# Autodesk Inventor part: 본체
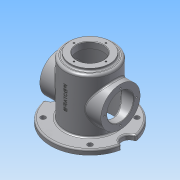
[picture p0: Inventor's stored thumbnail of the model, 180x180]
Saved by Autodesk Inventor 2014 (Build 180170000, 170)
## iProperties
Created: 2018-04
Part Number: 본체
Material: 알루미늄 6061
Document SubType Name: Modeling
Designer: user
Density: 2.71 g/cm^3
Appearance: 알루미늄 - 평지
Mass: 1151.3 g
Surface Area: 1200.36 cm^2
Volume: 424.833 cm^3
Author: user
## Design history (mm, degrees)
sketch "스케치1"
  geometry: L1 (-62, 0)-(62, 0); L2 (-62, 0)-(-62, 27); L3 (-62, 27)-(62, 27); L4 (62, 27)-(62, 0); L5 (-62, 27)-(-62, 40); L6 (-62, 40)-(62, 40); L7 (62, 40)-(62, 27); 2 further points
  constraints: 14 end point, 3 parallel, 3 perpendicular, 1 coincident, 1 horizontal, 1 midpoint
  dimensions: "d0" = 124 distance of L1.start L1.end; "d1" = 54 diameter of L3 L1; "d2" = 80 diameter of L6 L1
revolve "회전1" stored, may be unused: angle "d3" = 90 deg
sketch "스케치3"
  geometry: L1 (0, 65)-(0, -68); L2 (62, 40)-(62, -40) reference; L3 (62, -40)-(-62, -40) reference; L4 (-62, -40)-(-62, 40) reference; L5 (-62, 40)-(62, 40) reference; L6 (0, 65)-(-40, 65); L7 (-40, 65)-(-40, 60); L8 (-40, 60)-(-50, 60); L9 (-50, 60)-(-50, -68); L10 (-50, -68)-(0, -68); L11 (-27, 65)-(-27, 52); L12 (-27, 52)-(-45, 52); L13 (-45, 52)-(-45, -68); 2 further points
  constraints: 18 end point, 4 parallel, 4 perpendicular, 2 point on line, 1 midpoint, 1 vertical, 1 vertical alignment
  dimensions: "d13" = 133 distance of L1.start L1.end; "d14" = 80 diameter of L7 L1; "d15" = 100 diameter of L9 L1; "d16" = 54 diameter of L11 L1; "d17" = 90 diameter of L13 L1; "d18" = 5 distance of L6.end L7.end; "d19" = 13 distance of L11.start L11.end; "d20" = 60 distance from line of L8 point (0, 0)
  node "절단 모서리 투영2"
revolve "회전3" stored, may be unused: angle "d21" = 90 deg
node "작업 평면1"
sketch "스케치4"
  geometry: L1 (0, 0)-(47.73, 47.73); L2 (0, 0)-(67.5, 0); C1 r 50 at (0, 0) reference; C2 r 80 at (0, 0); C3 r 5 at (47.73, 47.73); C4 r 5 at (-47.73, 47.73); C5 r 5 at (-47.73, -47.73); C6 r 5 at (47.73, -47.73); 1 further point
  constraints: 5 centre point, 4 end point, 2 coincident, 1 equal length, 1 horizontal, 9 other
  dimensions: "d23" = 160 diameter of C2; "d25" = 67.5 distance of L1.start L1.end; "d26" = 45 deg angle of L2 L1; "d27" = 10 diameter of C3; "d30" = 360 deg dimension on point (0, 0) C3.centre (derived)
extrude "돌출1" join sketch "스케치4" distance "d32" = 10; taper "d33" = 0 deg
sketch "스케치5"
  geometry: C1 r 50 at (0, 0) reference; C2 r 15 at (-80, 0); C3 r 15 at (80, 0); A1 r 80 centre (0, 0) between (-80, 0) and (80, 0) reference
  constraints: 2 centre point, 2 horizontal alignment, 2 point on circle
  dimensions: "d36" = 30 diameter of C2; "d37" = 30 diameter of C3
extrude "돌출2" cut sketch "스케치5" distance "d38" = 10; taper "d39" = 0 deg
revolve "회전4" stored, may be unused: angle "d40" = 90 deg
revolve "회전5" stored, may be unused: angle "d41" = 90 deg
sketch "스케치6"
  geometry: C1 r 27 at (0, 0) reference; 4 further points
  constraints: 1 vertical alignment, 5 other
  dimensions: "d42" = 32.5 distance of C1.centre point (0, 32.5); "d45" = 360 deg dimension on C1.centre point (0, 32.5) (derived)
hole "구멍1" sketch "스케치6" at (0, 32.5), (-32.5, 0), (0, -32.5), (32.5, 0) diameter "d47" = 3.242; stored, may be unused: countersink angle "d51" = 90 deg, drill point angle "d53" = 118 deg; dims "d48" = 8, "d49" = 4, "d50" = 2, "d52" = 10
sketch "스케치7"
  geometry: C1 r 27 at (0, 0) reference; 4 further points
  constraints: 1 vertical alignment, 5 other
  dimensions: "d54" = 32.5 distance of C1.centre point (0, 32.5); "d57" = 360 deg dimension on C1.centre point (0, 32.5) (derived)
hole "구멍2" sketch "스케치7" at (0, 32.5), (-32.5, 0), (0, -32.5), (32.5, 0) diameter "d59" = 3.242; stored, may be unused: countersink angle "d63" = 90 deg, drill point angle "d65" = 118 deg; dims "d60" = 8, "d61" = 4, "d62" = 2, "d64" = 10
fillet "모깎기1" dims "d66" = 5
fillet "모깎기2" dims "d67" = 3
fillet "모깎기3" dims "d68" = 3
fillet "모깎기4" dims "d69" = 3
fillet "모깎기5" dims "d70" = 3
chamfer "모따기1" distance "d71" = 1; stored, may be unused: second distance "d72" = 2, angle "d73" = 45 deg
node "작업 평면2"
sketch "스케치8"
  geometry: L1 (-77.955, -56)-(77.955, -56) reference; 2 further points
  constraints: 1 vertical alignment, 1 other
  dimensions: "d74" = 70 distance from line of L1 point (0, 14)
feature "엠보싱1" sketch "스케치8" dims "d75" = 0.5, "d76" = 0
node "솔리드1"
mirror "대칭1"
node "절단 모서리 투영3"
